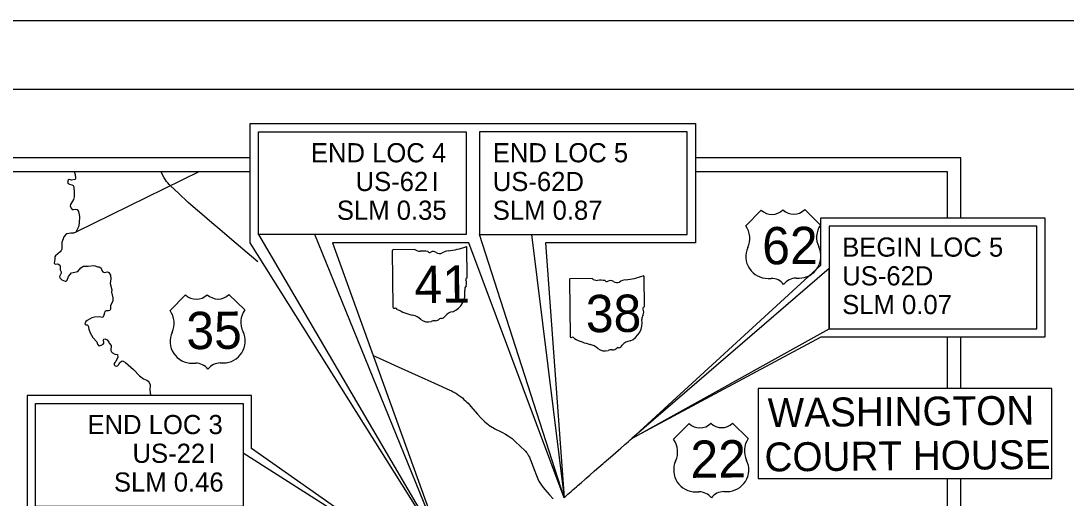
# Model space of a CAD drawing. Extents: x -12 to 164, y -741 to 24.
# Drawn here: x 5.3 to 12.93, y 18.51 to 22 of the extents above; entities that cross this region are included whole.
import ezdxf

# ---------------------------------------------------------------- set-up
doc = ezdxf.new("R2010")
doc.units = 0
for name, color, linetype in [('Default', 7, 'Continuous'), ('PM_P_Channelizing_Line', 7, 'Continuous'), ('PM_P_Crosswalk', 7, 'Continuous'), ('PM_P_Parking_Lot_Stall', 7, 'Continuous'), ('PM_P_Stop_Line', 7, 'Continuous'), ('PM_X_CL_Pass_Proh_Rt', 7, 'Continuous'), ('PM_X_Edge_Line', 7, 'Continuous'), ('SH_Border', 7, 'Continuous'), ('SH_Cut_Line', 7, 'Continuous'), ('SH_Data', 7, 'Continuous'), ('SH_Text', 7, 'Continuous')]:
    doc.layers.add(name, color=color, linetype=linetype)

msp = doc.modelspace()

# ---------------------------------------------------------------- linework, layer by layer
at = {"layer": 'PM_P_Channelizing_Line'}
msp.add_line((6.6045, 20.9), (5.7023, 20.4571), dxfattribs=at)
msp.add_lwpolyline([(5.6904, 20.9), (5.6975, 20.878), (5.7006, 20.8507), (5.6963, 20.8422), (5.6712, 20.837), (5.6627, 20.8397), (5.6542, 20.8406), (5.6463, 20.8364), (5.6415, 20.8201), (5.6466, 20.8116), (5.6557, 20.8064), (5.674, 20.8028), (5.6822, 20.7969), (5.6867, 20.7881), (5.6909, 20.7464), (5.689, 20.7134), (5.6841, 20.6942), (5.6643, 20.6592), (5.6616, 20.6485), (5.6626, 20.6404), (5.668, 20.631), (5.6766, 20.6229), (5.6857, 20.6224), (5.7033, 20.6256), (5.7115, 20.6229), (5.7211, 20.6067), (5.7292, 20.5706), (5.7272, 20.5219), (5.7214, 20.4955), (5.7023, 20.4571), (5.6854, 20.4487), (5.6652, 20.4501), (5.6364, 20.4433), (5.6285, 20.4385), (5.6152, 20.4214), (5.5989, 20.3805), (5.5996, 20.3321), (5.5963, 20.3227), (5.5888, 20.3138), (5.5526, 20.2843), (5.5495, 20.2764), (5.5494, 20.2585), (5.5436, 20.2308), (5.5506, 20.2215), (5.5679, 20.2251), (5.5767, 20.222), (5.5856, 20.2149), (5.5872, 20.2067), (5.5872, 20.1822), (5.5961, 20.1654), (5.5962, 20.1575), (5.5826, 20.132), (5.5855, 20.1235), (5.601, 20.1079), (5.6241, 20.0975), (5.6329, 20.0976), (5.6394, 20.1058), (5.6489, 20.1329), (5.671, 20.1582), (5.7162, 20.1696), (5.7396, 20.1958), (5.758, 20.2073), (5.7668, 20.2089), (5.7923, 20.207), (5.8344, 20.2121), (5.8435, 20.2112), (5.8609, 20.2041), (5.8694, 20.2033), (5.8782, 20.2005), (5.8861, 20.1937), (5.8929, 20.1758), (5.9002, 20.1655), (5.9081, 20.1628), (5.9336, 20.1658), (5.9424, 20.1615), (5.9561, 20.1434), (5.9576, 20.1161), (5.9538, 20.0803), (5.9662, 20.0358), (5.9638, 20.0188), (5.9724, 19.9778), (5.9723, 19.9526), (5.9562, 19.9195), (5.9565, 19.8932), (5.9496, 19.8843), (5.9412, 19.8814), (5.9248, 19.8813), (5.9151, 19.8758), (5.9105, 19.8673), (5.9075, 19.85), (5.8988, 19.8327), (5.8739, 19.8375), (5.8384, 19.835), (5.818, 19.8298), (5.7839, 19.8116), (5.7758, 19.8043), (5.769, 19.7869), (5.776, 19.7788), (5.7842, 19.7799), (5.7921, 19.7718), (5.7961, 19.7479), (5.8067, 19.7217), (5.8259, 19.6876), (5.8545, 19.6543), (5.8597, 19.6373), (5.8673, 19.6286), (5.8752, 19.6271), (5.8928, 19.6326), (5.9018, 19.6377), (5.9068, 19.6462), (5.907, 19.6547), (5.9019, 19.665), (5.9069, 19.6742), (5.9147, 19.6768), (5.9305, 19.67), (5.9429, 19.6525), (5.9455, 19.6447), (5.9595, 19.6285), (5.9579, 19.5911), (5.9621, 19.5817), (5.9703, 19.574), (5.9877, 19.565), (6.0069, 19.5617), (6.0093, 19.5442), (5.9942, 19.5107), (5.9864, 19.5047), (5.9814, 19.4965), (5.9825, 19.4874), (5.9888, 19.479), (5.9967, 19.4765), (6.0058, 19.4807), (6.0139, 19.4883), (6.0244, 19.505), (6.0407, 19.5155), (6.0486, 19.5137), (6.065, 19.5035), (6.124, 19.4532), (6.1675, 19.4071), (6.1972, 19.3857), (6.2219, 19.374), (6.2307, 19.3684), (6.2383, 19.359), (6.2442, 19.3412), (6.2429, 19.3016), (6.2477, 19.2662), (6.2475, 19.2641)], dxfattribs=at)
at = {"layer": 'PM_P_Crosswalk'}
for points in [[(9.4206, 18.6505), (9.4275, 18.6566), (9.4564, 18.6819), (9.4911, 18.7124), (9.5529, 18.7664), (9.5597, 18.7723), (9.5917, 18.8), (9.607, 18.8133), (9.6644, 18.863), (9.6828, 18.879), (9.7124, 18.9048), (9.7215, 18.9128), (9.7388, 18.928), (9.7505, 18.9379), (9.7619, 18.9478)], [(9.2674, 18.5162), (9.2831, 18.5296), (9.2963, 18.5413), (9.3197, 18.5614), (9.3217, 18.5632), (9.3349, 18.5754), (9.346, 18.5849), (9.3583, 18.5954), (9.3711, 18.6067), (9.3928, 18.6261), (9.4206, 18.6505)]]:
    msp.add_lwpolyline(points, dxfattribs=at)
at = {"layer": 'PM_P_Parking_Lot_Stall'}
for p, q in [((8.0136, 20.3208), (8.0175, 19.9073)), ((8.1784, 20.3294), (8.0189, 20.3279)), ((8.5603, 20.1269), (8.5582, 20.3432)), ((8.5602, 20.127), (8.5603, 20.1269)), ((9.3074, 20.1081), (9.3113, 19.6945)), ((9.4722, 20.1167), (9.3127, 20.1152)), ((9.8541, 19.9142), (9.852, 20.1305)), ((9.854, 19.9143), (9.8541, 19.9142))]:
    msp.add_line(p, q, dxfattribs=at)
for centre, radius, start, end in [((8.0198, 20.3217), 0.00631, 98.66865, 188.66865), ((8.216, 20.3778), 0.0612, 232.15805, 271.65043), ((8.2389, 20.0978), 0.2198, 81.02524, 95.52682), ((8.2867, 20.3264), 0.0177, 220.33061, 297.64092), ((8.313, 20.2788), 0.0367, 55.00523, 119.67968), ((8.3598, 20.3448), 0.0442, 234.39475, 295.36674), ((8.4391, 20.2056), 0.1162, 97.88473, 121.3074), ((8.359, 20.8949), 0.5778, 276.38302, 289.445), ((8.5522, 20.3441), 0.00607, 352.40063, 98.27655), ((8.559, 20.111), 0.00939, 108.48253, 210.87551), ((8.4996, 20.0831), 0.0563, 340.57151, 24.18811), ((8.5538, 20.126), 0.00649, 290.14236, 8.27268), ((9.3136, 20.109), 0.00631, 98.66865, 188.66865), ((9.5098, 20.1651), 0.0612, 232.15805, 271.65043), ((9.5327, 19.8851), 0.2198, 81.02524, 95.52682), ((9.5805, 20.1136), 0.0177, 220.33061, 297.64092), ((9.6068, 20.0661), 0.0367, 55.00523, 119.67968), ((9.6536, 20.1321), 0.0442, 234.39475, 295.36674), ((9.733, 19.9929), 0.1162, 97.88473, 121.3074), ((9.6528, 20.6822), 0.5778, 276.38302, 289.445), ((9.846, 20.1314), 0.00607, 352.40063, 98.27655), ((8.3997, 20.0074), 0.1445, 292.84743, 9.52439), ((8.5828, 20.0366), 0.041, 137.34504, 187.46814), ((8.0238, 19.9064), 0.00637, 172.49693, 258.84516), ((8.0243, 19.9487), 0.0486, 267.87754, 281.1424), ((8.0349, 19.8836), 0.0175, 30.28693, 93.81029), ((8.2526, 20.2572), 0.4172, 240.95147, 257.73705), ((8.1332, 19.7226), 0.1305, 47.7227, 76.37452), ((8.4626, 19.7953), 0.0791, 94.94167, 143.1153), ((9.8767, 19.8239), 0.041, 137.34504, 187.46814), ((9.8528, 19.8983), 0.00939, 108.48253, 210.87551), ((9.7934, 19.8704), 0.0563, 340.57151, 24.18811), ((9.8476, 19.9133), 0.00649, 290.14236, 8.27268), ((8.2729, 19.8837), 0.0828, 231.23892, 286.83038), ((8.3221, 19.7412), 0.0681, 86.23367, 111.74849), ((8.3271, 19.8533), 0.0441, 269.31557, 316.08782), ((8.3674, 19.8136), 0.0124, 66.29028, 133.18697), ((8.3616, 19.8704), 0.0467, 283.41174, 323.81566), ((9.6935, 19.7947), 0.1445, 292.84743, 9.52439), ((9.3176, 19.6937), 0.00637, 172.49693, 258.84516), ((9.3182, 19.736), 0.0486, 267.87754, 281.1424), ((9.3287, 19.6709), 0.0175, 30.28693, 93.81029), ((9.5464, 20.0445), 0.4172, 240.95147, 257.73705), ((9.4271, 19.5098), 0.1305, 47.7227, 76.37452), ((9.6554, 19.6577), 0.0467, 283.41174, 323.81566), ((9.7564, 19.5826), 0.0791, 94.94167, 143.1153), ((9.5667, 19.671), 0.0828, 231.23892, 286.83038), ((9.616, 19.5285), 0.0681, 86.23367, 111.74849), ((9.621, 19.6406), 0.0441, 269.31557, 316.08782), ((9.6613, 19.6009), 0.0124, 66.29028, 133.18697)]:
    msp.add_arc(centre, radius, start, end, dxfattribs=at)
at = {"layer": 'PM_P_Stop_Line'}
for p, q in [((10.7075, 20.6178), (10.595, 20.5032)), ((11.1398, 20.5084), (11.0253, 20.6208)), ((10.7576, 20.1188), (10.7803, 20.119)), ((10.9619, 20.1207), (10.9846, 20.1209)), ((6.9353, 19.8887), (6.8208, 20.0012)), ((6.5029, 19.9982), (6.3905, 19.8836)), ((6.553, 19.4992), (6.5757, 19.4994)), ((6.7573, 19.5011), (6.7801, 19.5013)), ((10.1803, 19.0583), (10.0678, 18.9437)), ((10.6127, 18.9489), (10.4981, 19.0613)), ((10.2304, 18.5593), (10.2531, 18.5595)), ((10.4347, 18.5612), (10.4574, 18.5615))]:
    msp.add_line(p, q, dxfattribs=at)
for centre, radius, start, end in [((10.7862, 20.6996), 0.1135, 226.11154, 314.96555), ((10.9451, 20.7011), 0.1135, 226.11154, 314.96555), ((10.4657, 20.4109), 0.1589, 335.08567, 35.53948), ((11.2709, 20.4184), 0.1589, 145.53762, 205.99142), ((10.7543, 20.2777), 0.1589, 155.37047, 271.17681), ((10.9848, 20.2799), 0.1589, 269.90028, 25.70663), ((10.7813, 20.0055), 0.1135, 37.40844, 90.53855), ((10.9629, 20.0072), 0.1135, 90.53855, 143.66865), ((6.5816, 20.08), 0.1135, 226.11154, 314.96555), ((6.7405, 20.0815), 0.1135, 226.11154, 314.96555), ((6.2612, 19.7913), 0.1589, 335.08567, 35.53948), ((7.0664, 19.7988), 0.1589, 145.53762, 205.99142), ((6.5498, 19.6581), 0.1589, 155.37047, 271.17681), ((6.7803, 19.6603), 0.1589, 269.90028, 25.70663), ((6.5768, 19.3859), 0.1135, 37.40844, 90.53855), ((6.7584, 19.3876), 0.1135, 90.53855, 143.66865), ((10.259, 19.1401), 0.1135, 226.11154, 314.96555), ((10.4179, 19.1416), 0.1135, 226.11154, 314.96555), ((9.9385, 18.8514), 0.1589, 335.08567, 35.53948), ((10.7437, 18.8589), 0.1589, 145.53762, 205.99142), ((10.2271, 18.7182), 0.1589, 155.37047, 271.17681), ((10.4577, 18.7204), 0.1589, 269.90028, 25.70663), ((10.2541, 18.446), 0.1135, 37.40844, 90.53855), ((10.4357, 18.4477), 0.1135, 90.53855, 143.66865)]:
    msp.add_arc(centre, radius, start, end, dxfattribs=at)
at = {"layer": 'PM_X_Edge_Line'}
msp.add_line((7.1139, 20.1589), (7.1155, 20.1575), dxfattribs=at)
for points in [[(7.0315, 20.2389), (6.9841, 20.2795), (6.842, 20.4001), (6.7542, 20.4747), (6.6949, 20.5254), (6.622, 20.5873), (6.5594, 20.6409), (6.539, 20.6585), (6.5218, 20.6742), (6.4515, 20.7402), (6.3947, 20.7944), (6.3831, 20.8055), (6.3731, 20.8163), (6.3646, 20.8266), (6.3561, 20.8384), (6.3469, 20.8529), (6.3236, 20.9)], [(7.8736, 19.5559), (7.9179, 19.5359), (8.0567, 19.4733), (8.203, 19.4073), (8.3221, 19.354), (8.4336, 19.3032), (8.4429, 19.2984), (8.4589, 19.29), (8.4774, 19.2791), (8.4856, 19.274), (8.4962, 19.2665), (8.5115, 19.2556), (8.5249, 19.2448), (8.5368, 19.2347), (8.5478, 19.2249), (8.5588, 19.2141), (8.5667, 19.2058), (8.5775, 19.1943), (8.5872, 19.1829), (8.6364, 19.1272), (8.6612, 19.0987), (8.6763, 19.0824), (8.6897, 19.0696), (8.7006, 19.0602), (8.7102, 19.0526), (8.7195, 19.0455), (8.7296, 19.0389), (8.7425, 19.031), (8.7518, 19.0259), (8.7627, 19.0202), (8.8123, 18.9941), (8.84, 18.9797), (8.86, 18.9686), (8.8674, 18.9641), (8.8737, 18.9596), (8.8811, 18.9541), (8.8881, 18.9483), (8.8967, 18.9405), (8.9142, 18.924), (8.944, 18.8955), (8.9855, 18.8554), (8.9904, 18.8491), (8.9972, 18.8405), (9.0033, 18.832), (9.0093, 18.8219), (9.0145, 18.8121), (9.0209, 18.7974), (9.0276, 18.7798), (9.0447, 18.7341), (9.0709, 18.6656), (9.0755, 18.6547), (9.0788, 18.6471), (9.0835, 18.638), (9.0886, 18.6294), (9.0977, 18.6159), (9.1083, 18.6006), (9.1283, 18.5766), (9.1611, 18.5381), (9.1889, 18.5069)]]:
    msp.add_lwpolyline(points, dxfattribs=at)
at = {"layer": 'SH_Border'}
msp.add_lwpolyline([(1.5, 21.5), (33.5, 21.5), (33.5, 0.5), (1.5, 0.5)], close=True, dxfattribs=at)
at = {"layer": 'SH_Cut_Line'}
msp.add_lwpolyline([(0, 0), (34, 0), (34, 22), (0, 22)], close=True, dxfattribs=at)
at = {"layer": 'SH_Data'}
for p, q in [((12.0655, 19.6892), (12.0655, 19.3133)), ((12.1655, 19.3133), (12.1655, 19.6892))]:
    msp.add_line(p, q, dxfattribs=at)
for points in [[(8.5537, 20.4387), (7.0366, 20.4387), (7.0366, 21.1901), (8.5537, 21.1901)], [(8.6508, 20.4387), (10.1679, 20.4387), (10.1679, 21.1901), (8.6508, 21.1901)], [(11.2028, 19.7492), (12.7199, 19.7492), (12.7199, 20.5007), (11.2028, 20.5007)], [(7.0366, 20.4387), (8.3853, 18.1356), (7.4488, 20.4387)], [(9.0302, 20.4387), (9.2674, 18.516), (8.6508, 20.4387)], [(11.2028, 20.19), (9.7619, 18.9477), (11.2028, 19.7492)], [(6.9246, 18.4527), (5.4075, 18.4527), (5.4075, 19.2041), (6.9246, 19.2041)], [(6.9246, 18.4527), (8.1401, 18.0676), (6.9246, 18.8405)]]:
    msp.add_lwpolyline(points, close=True, dxfattribs=at)
for points in [[(6.9766, 21), (2, 21), (2, 8.9058), (12.1655, 8.9058), (12.1655, 18.6562)], [(12.1655, 20.5607), (12.1655, 21), (10.2279, 21)], [(12.0655, 18.6562), (12.0655, 9.0058), (2.1, 9.0058), (2.1, 20.9), (6.9766, 20.9)], [(10.2279, 20.9), (12.0655, 20.9), (12.0655, 20.5607)]]:
    msp.add_lwpolyline(points, dxfattribs=at)
at = {"layer": 'SH_Text'}
for p, q in [((6.9766, 21.2501), (10.2279, 21.2501)), ((6.9766, 20.3787), (6.9766, 21.2501)), ((10.2279, 21.2501), (10.2279, 20.3787)), ((11.1428, 20.5607), (12.7799, 20.5607)), ((11.1428, 20.2146), (11.1428, 20.5607)), ((12.7799, 20.5607), (12.7799, 19.6892)), ((8.3853, 18.1356), (6.9766, 20.3787)), ((8.573, 20.3787), (7.5771, 20.3787)), ((7.5771, 20.3787), (8.3853, 18.1356)), ((9.2674, 18.516), (8.573, 20.3787)), ((10.2279, 20.3787), (9.1323, 20.3787)), ((9.1323, 20.3787), (9.2674, 18.516)), ((9.7619, 18.9477), (11.1428, 20.2146)), ((11.1428, 19.6892), (9.7619, 18.9477)), ((12.7799, 19.6892), (11.1428, 19.6892)), ((6.9846, 19.2641), (5.3475, 19.2641)), ((5.3475, 19.2641), (5.3475, 18.3927)), ((6.9846, 18.8746), (6.9846, 19.2641)), ((8.1401, 18.0676), (6.9846, 18.8746))]:
    msp.add_line(p, q, dxfattribs=at)
msp.add_lwpolyline([(12.8309, 19.3133), (10.6863, 19.3133), (10.6863, 18.6562), (12.8309, 18.6562)], close=True, dxfattribs=at)

# ---------------------------------------------------------------- texts
at = {"layer": 'Default'}
for s, p in [('END LOC 4', (7.4187, 20.9668)), ('END LOC 5', (8.7471, 20.9668)), ('US-62', (7.7452, 20.7568)), ('I', (8.2996, 20.7568)), ('US-62D', (8.7471, 20.7568)), ('SLM 0.35', (7.6088, 20.5468)), ('SLM 0.87', (8.7471, 20.5468)), ('BEGIN LOC 5', (11.2991, 20.2774)), ('US-62D', (11.2991, 20.0674)), ('SLM 0.07', (11.2991, 19.8574)), ('END LOC 3', (5.787, 18.9808)), ('US-22', (6.1161, 18.7708)), ('I', (6.6704, 18.7708)), ('SLM 0.46', (5.9806, 18.5608))]:
    msp.add_text(s, height=0.14, dxfattribs=at).set_placement(p)
at = {"layer": 'PM_P_Parking_Lot_Stall'}
for s, p in [('41', (8.1766, 19.9379)), ('38', (9.4277, 19.7248))]:
    msp.add_text(s, height=0.27243, rotation=0.53855, dxfattribs=at).set_placement(p)
at = {"layer": 'PM_P_Stop_Line'}
for s, p in [('62', (10.7159, 20.2206)), ('35', (6.5105, 19.601)), ('22', (10.1921, 18.6611))]:
    msp.add_text(s, height=0.27243, rotation=0.53855, dxfattribs=at).set_placement(p)
at = {"layer": 'PM_X_CL_Pass_Proh_Rt'}
for s, height, p in [('WASHINGTON', 0.21134, (10.7559, 19.0319)), ('COURT HOUSE', 0.211336, (10.7324, 18.7076))]:
    msp.add_text(s, height=height, rotation=0.53856, dxfattribs=at).set_placement(p)

doc.saveas('drawing.dxf')
